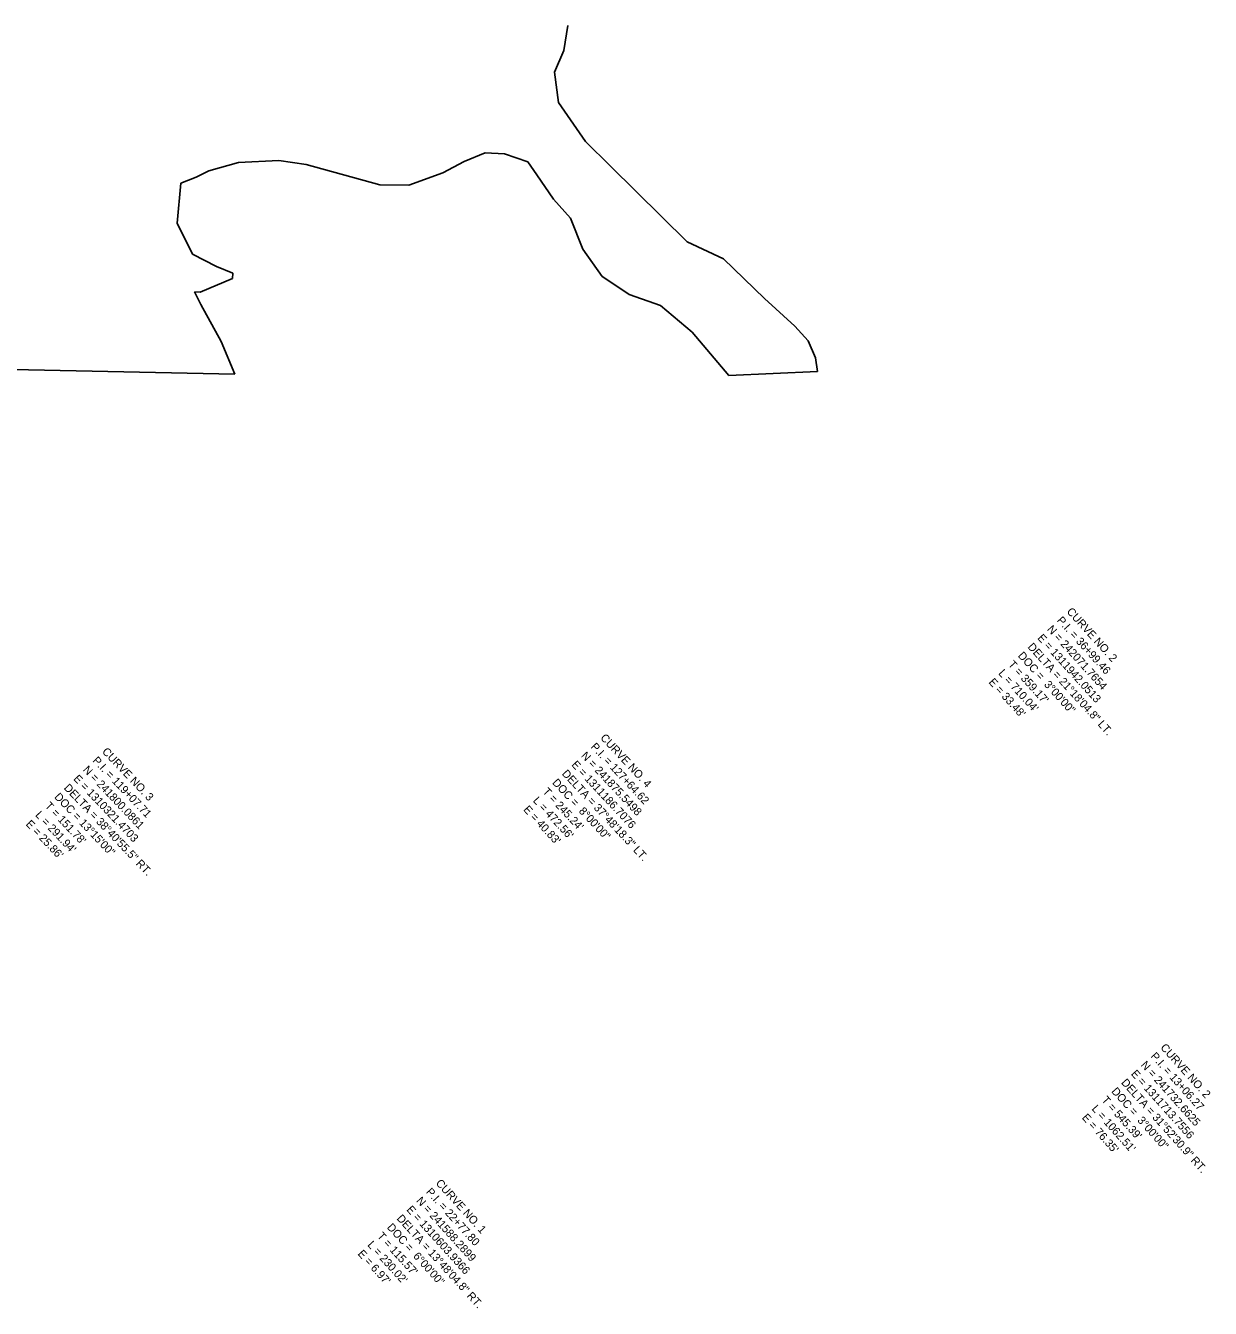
# Model space of a CAD drawing. Extents: x 1300404 to 1323571, y 234004 to 252077.
# Drawn here: x 1314648 to 1316719, y 236181 to 238424 of the extents above; entities that cross this region are included whole.
import ezdxf

# ---------------------------------------------------------------- set-up
doc = ezdxf.new("R2010")
doc.units = 0
doc.layers.add('R_Curve Data OLD', color=7, linetype='Continuous')
doc.layers.add('R_Flooplain', color=7, linetype='Continuous')

msp = doc.modelspace()

# ---------------------------------------------------------------- linework, layer by layer
at = {"layer": 'R_Flooplain'}
for p, q in [((1315595.8, 238424.4), (1315588.8, 238381.2)), ((1315588.8, 238381.2), (1315572.4, 238343.3)), ((1315572.4, 238343.3), (1315579.4, 238289.7)), ((1315579.4, 238289.7), (1315626.9, 238222)), ((1315626.9, 238222), (1315670.7, 238178.7)), ((1315020.1, 238184.8), (1314968.6, 238170.5)), ((1315090.5, 238188.5), (1315020.1, 238184.8)), ((1315138.5, 238181.3), (1315090.5, 238188.5)), ((1315267.4, 238145.8), (1315138.5, 238181.3)), ((1315414.6, 238186.7), (1315377.3, 238166.8)), ((1315451.6, 238201.8), (1315414.6, 238186.7)), ((1315485.4, 238200.1), (1315451.6, 238201.8)), ((1315525.9, 238186), (1315485.4, 238200.1)), ((1315541.7, 238163.4), (1315525.9, 238186)), ((1314946.3, 238159.5), (1314919.1, 238148.8)), ((1314968.6, 238170.5), (1314946.3, 238159.5)), ((1315377.3, 238166.8), (1315318.2, 238145.6)), ((1315571, 238120.8), (1315541.7, 238163.4)), ((1315670.7, 238178.7), (1315804.4, 238046.1)), ((1314919.1, 238148.8), (1314913.2, 238078.9)), ((1315318.2, 238145.6), (1315267.4, 238145.8)), ((1315600.8, 238087.8), (1315571, 238120.8)), ((1314913.2, 238078.9), (1314939.5, 238024.4)), ((1315622.3, 238033.5), (1315600.8, 238087.8)), ((1315804.4, 238046.1), (1315868.2, 238016.3)), ((1314939.5, 238024.4), (1314982, 238002.9)), ((1315656.2, 237985.8), (1315622.3, 238033.5)), ((1314982, 238002.9), (1315010.5, 237991.7)), ((1315868.2, 238016.3), (1315939.8, 237947.3)), ((1315010, 237982.1), (1314953.2, 237958.3)), ((1315010.5, 237991.7), (1315010, 237982.1)), ((1315679.6, 237970.1), (1315656.2, 237985.8)), ((1314953.2, 237958.3), (1314943.5, 237958.8)), ((1314943.5, 237958.8), (1314954.5, 237936.5)), ((1315703.1, 237954.4), (1315679.6, 237970.1)), ((1314954.5, 237936.5), (1314990, 237871.8)), ((1315757.7, 237934.7), (1315703.1, 237954.4)), ((1315813.5, 237888.4), (1315757.7, 237934.7)), ((1315939.8, 237947.3), (1315993, 237898.7)), ((1315877.5, 237812.6), (1315813.5, 237888.4)), ((1315993, 237898.7), (1316016, 237873.3)), ((1314990, 237871.8), (1315013.8, 237815)), ((1316016, 237873.3), (1316029, 237843.6)), ((1315013.8, 237815), (1313450, 237847.8)), ((1316029, 237843.6), (1316032.6, 237819.3)), ((1316032.6, 237819.3), (1315877.5, 237812.6))]:
    msp.add_line(p, q, dxfattribs=at)

# ---------------------------------------------------------------- texts
at = {"layer": 'R_Curve Data OLD'}
for s, rotation, p in [('CURVE NO. 2', 312.132, (1316467.1, 237398.8)), ('N = 242071.7654', 312.132, (1316433, 237367.9)), ('P.I. = 36+99.46', 312.132, (1316450.1, 237383.3)), ('E = 1311942.0513', 312.132, (1316416, 237352.5)), ('DOC =  3%%d00\'00"', 312.132, (1316381.8, 237321.6)), ('DELTA = 21%%d18\'04.8" LT.', 312.132, (1316398.9, 237337)), ("T = 359.17'", 312.132, (1316364.8, 237306.2)), ("E = 33.48'", 312.132, (1316330.7, 237275.3)), ("L = 710.04'", 312.132, (1316347.7, 237290.8)), ('P.I. = 127+64.62', 312.9969, (1315635, 237162.1)), ('CURVE NO. 4', 312.9969, (1315651.8, 237177.8)), ('CURVE NO. 3', 313.5491, (1314780.7, 237153.6)), ('N = 241875.5498', 312.9969, (1315618.2, 237146.5)), ('N = 241800.0861', 313.5491, (1314747.4, 237121.9)), ('P.I. = 119+07.71', 313.5491, (1314764, 237137.8)), ('E = 1311186.7076', 312.9969, (1315601.4, 237130.8)), ('E = 1310321.4703', 313.5491, (1314730.7, 237106.1)), ('DOC =  8%%d00\'00"', 312.9969, (1315567.7, 237099.4)), ('DELTA = 37%%d48\'18.3" LT.', 312.9969, (1315584.6, 237115.1)), ('DOC = 13%%d15\'00"', 313.5491, (1314697.3, 237074.4)), ('DELTA = 38%%d40\'55.5" RT.', 313.5491, (1314714, 237090.2)), ("T = 245.24'", 312.9969, (1315550.9, 237083.7)), ("T = 151.78'", 313.5491, (1314680.7, 237058.5)), ("E = 40.83'", 312.9969, (1315517.3, 237052.3)), ("L = 472.56'", 312.9969, (1315534.1, 237068)), ("L = 291.94'", 313.5491, (1314664, 237042.7)), ("E = 25.86'", 313.5491, (1314647.3, 237026.8)), ('CURVE NO. 2', 311.7648, (1316631, 236636.2)), ('N = 241732.6625', 311.7648, (1316596.7, 236605.6)), ('P.I. = 13+06.27', 311.7648, (1316613.9, 236620.9)), ('E = 1311713.7556', 311.7648, (1316579.6, 236590.2)), ('DOC =  3%%d00\'00"', 311.7648, (1316545.3, 236559.6)), ('DELTA = 31%%d52\'30.9" RT.', 311.7648, (1316562.4, 236574.9)), ("T = 545.39'", 311.7648, (1316528.1, 236544.3)), ("E = 76.35'", 311.7648, (1316493.8, 236513.6)), ("L = 1062.51'", 311.7648, (1316510.9, 236529)), ('P.I. = 22+77.80', 312.132, (1315347.1, 236383.5)), ('CURVE NO. 1', 312.132, (1315364.1, 236398.9)), ('N = 241588.2899', 312.132, (1315330, 236368)), ('DELTA = 13%%d48\'04.8" RT.', 312.132, (1315295.9, 236337.2)), ('E = 1310603.9366', 312.132, (1315313, 236352.6)), ('DOC =  6%%d00\'00"', 312.132, (1315278.9, 236321.7)), ("L = 230.02'", 312.132, (1315244.7, 236290.9)), ("T = 115.57'", 312.132, (1315261.8, 236306.3)), ("E = 6.97'", 312.132, (1315227.7, 236275.4))]:
    msp.add_text(s, height=14, rotation=rotation, dxfattribs=at).set_placement(p)

doc.saveas('drawing.dxf')
